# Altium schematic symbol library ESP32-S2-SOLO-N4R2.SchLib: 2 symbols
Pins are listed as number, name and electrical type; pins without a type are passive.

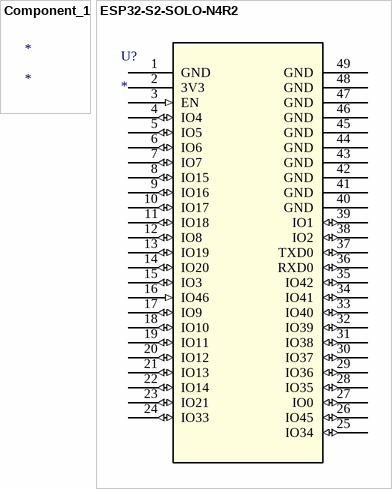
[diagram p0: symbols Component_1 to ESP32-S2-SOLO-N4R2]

## Component_1
designator *

## ESP32-S2-SOLO-N4R2
designator U?
No Description Available; Mfr_Name: Espressif Systems
footprint MOD41_ESP32-S2-SOLO_EXP
pins: 1 GND (power), 2 3V3 (power), 3 EN (in), 4 IO4 (io), 5 IO5 (io), 6 IO6 (io), 7 IO7 (io), 8 IO15 (io), 9 IO16 (io), 10 IO17 (io), 11 IO18 (io), 12 IO8 (io), 13 IO19 (io), 14 IO20 (io), 15 IO3 (io), 16 IO46 (in), 17 IO9 (io), 18 IO10 (io), 19 IO11 (io), 20 IO12 (io), 21 IO13 (io), 22 IO14 (io), 23 IO21 (io), 24 IO33 (io), 25 IO34 (io), 26 IO45 (io), 27 IO0 (io), 28 IO35 (io), 29 IO36 (io), 30 IO37 (io), 31 IO38 (io), 32 IO39 (io), 33 IO40 (io), 34 IO41 (io), 35 IO42 (io), 36 RXD0 (io), 37 TXD0 (io), 38 IO2 (io), 39 IO1 (io), 40 GND (power), 41 GND (power), 42 GND (power), 43 GND (power), 44 GND (power), 45 GND (power), 46 GND (power), 47 GND (power), 48 GND (power), 49 GND (power)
